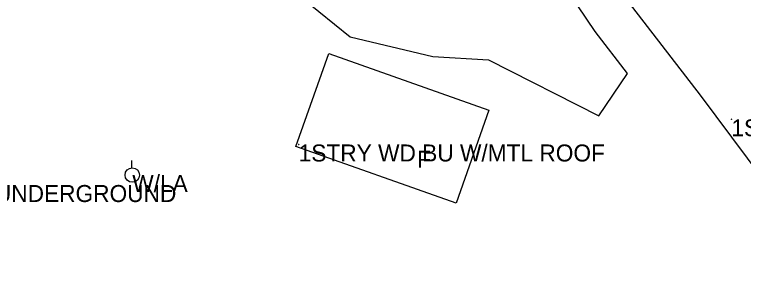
# Model space of a CAD drawing. Extents: x 1451369 to 1458940, y 1868647 to 1875095.
# Drawn here: x 1454143.2 to 1454358, y 1871239.9 to 1871314.6 of the extents above; entities that cross this region are included whole.
import ezdxf

# ---------------------------------------------------------------- set-up
doc = ezdxf.new("R2010")
doc.units = 0
for name, color, linetype in [('E_Const Align', 7, 'Continuous'), ('E_Property Line', 7, 'Continuous'), ('E_Proposed ROW and Easements', 7, 'Continuous'), ('S_BUILDING_ANNOT', 7, 'Continuous'), ('S_MISC_BOUNDARY', 7, 'Continuous'), ('S_PARKING', 7, 'Continuous'), ('S_SURVEY_TEXT_ANNOT', 7, 'Continuous'), ('S_UNDERGROUND_CABLE_ANNOT', 7, 'Continuous'), ('S_UTILITY_POLE_ANNOT', 7, 'Continuous')]:
    doc.layers.add(name, color=color, linetype=linetype)

msp = doc.modelspace()

# ---------------------------------------------------------------- linework, layer by layer
at = {"layer": 'E_Const Align'}
msp.add_line((1454177.77, 1871269.5), (1454177.77, 1871271.61), dxfattribs=at)
msp.add_circle((1454177.89, 1871267.36), 2.13, dxfattribs=at)
at = {"layer": 'E_Property Line'}
msp.add_lwpolyline([(1454235.8, 1871303.13), (1454282.99, 1871286.47), (1454273.32, 1871259.08), (1454226.13, 1871275.74)], close=True, dxfattribs=at)
at = {"layer": 'E_Proposed ROW and Easements'}
for points in [[(1454354.48, 1871283.75), (1454354.48, 1871283.8), (1454354.48, 1871283.75), (1454354.43, 1871283.75), (1454354.48, 1871283.75), (1454354.48, 1871283.7), (1454354.48, 1871283.75), (1454354.53, 1871283.75)], [(1454226.94, 1871276.34), (1454226.94, 1871276.39), (1454226.94, 1871276.34), (1454226.89, 1871276.34), (1454226.94, 1871276.34), (1454226.94, 1871276.29), (1454226.94, 1871276.34), (1454226.99, 1871276.34)]]:
    msp.add_lwpolyline(points, dxfattribs=at)
at = {"layer": 'S_MISC_BOUNDARY'}
msp.add_lwpolyline([(1454508.04, 1871132.59), (1454480.07, 1871123.31), (1454450.16, 1871133.48), (1454419.11, 1871179.34), (1454386.64, 1871235.64), (1454345.34, 1871290.82), (1454325.41, 1871316.62), (1454288.53, 1871360.43), (1454279.55, 1871373.71), (1454281.02, 1871384.44), (1454292.69, 1871389.73), (1454300.28, 1871390.19), (1454342.99, 1871366.06), (1454378.58, 1871316.67), (1454411.72, 1871280.3)], dxfattribs=at)
at = {"layer": 'S_PARKING'}
msp.add_lwpolyline([(1454175.25, 1871357.91), (1454187.26, 1871346.22), (1454208.3, 1871338.38), (1454223.66, 1871323.05), (1454242.1, 1871308.07), (1454266.52, 1871302.24), (1454282.9, 1871301.24), (1454315.4, 1871284.76), (1454323.88, 1871297.21), (1454314.37, 1871309.59), (1454301.45, 1871328.71), (1454286.62, 1871350.64), (1454269.62, 1871360.74), (1454257.03, 1871361.79), (1454244.36, 1871358.02), (1454223, 1871351.82), (1454213.28, 1871352.13), (1454198.42, 1871356.78), (1454186.28, 1871370.97)], dxfattribs=at)

# ---------------------------------------------------------------- texts
at = {"layer": 'S_BUILDING_ANNOT'}
msp.add_text('F', height=5, dxfattribs=at).set_placement((1454261.87, 1871269.52))
at = {"layer": 'S_SURVEY_TEXT_ANNOT'}
for s, p in [('1STRY WD STRG SHLTR', (1454354.48, 1871278.75)), ('1STRY WD BU W/MTL ROOF', (1454226.94, 1871271.34))]:
    msp.add_text(s, height=5, dxfattribs=at).set_placement(p)
at = {"layer": 'S_UNDERGROUND_CABLE_ANNOT'}
msp.add_text('UC GOES BACK UNDERGROUND', height=5, dxfattribs=at).set_placement((1454084.63, 1871259.41))
at = {"layer": 'S_UTILITY_POLE_ANNOT'}
msp.add_text('W/LA', height=5, dxfattribs=at).set_placement((1454177.89, 1871262.36))

doc.saveas('drawing.dxf')
